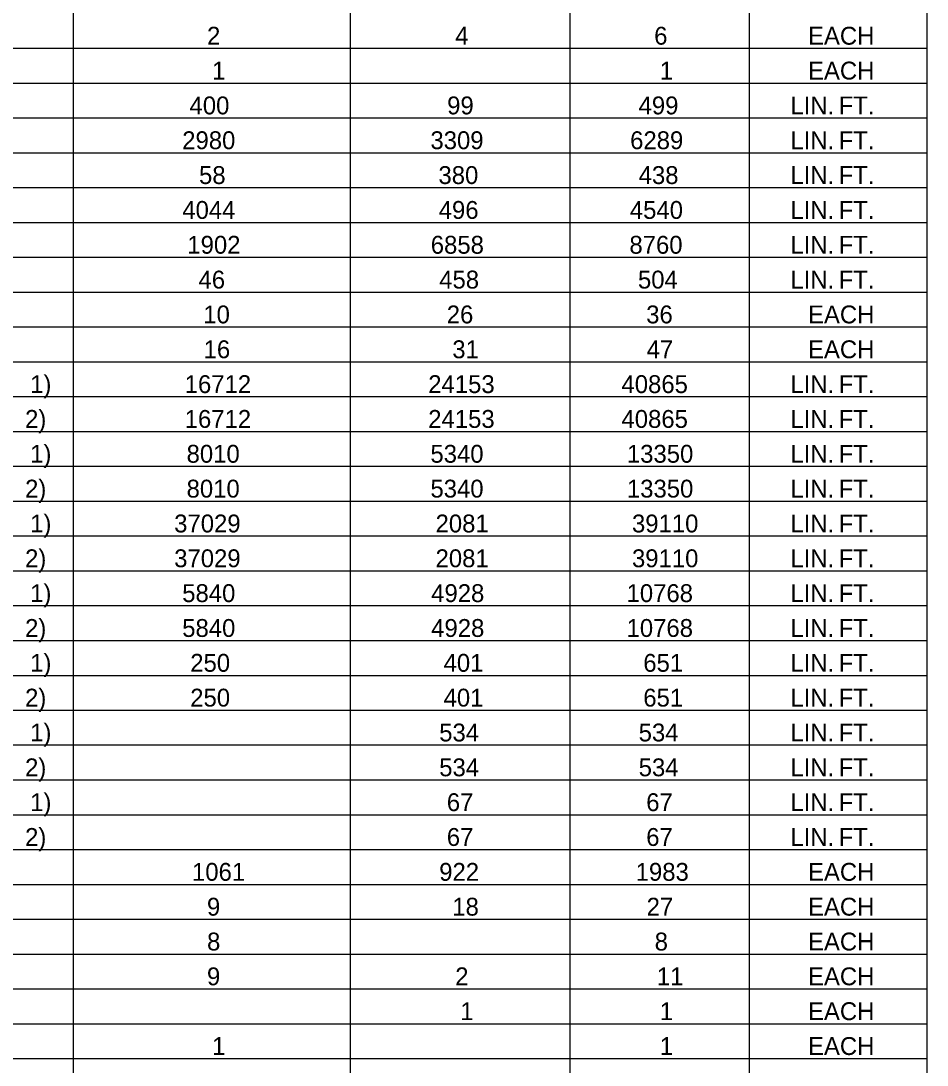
# Model space of a CAD drawing. Extents: x 1226603 to 1228117, y 151305 to 152343.
# Drawn here: x 1227709.6 to 1227925.2, y 151552.9 to 151801.3 of the extents above; entities that cross this region are included whole.
import ezdxf

# ---------------------------------------------------------------- set-up
doc = ezdxf.new("R2010")
doc.units = 0
doc.layers.add('R_Dimension', color=7, linetype='Continuous')

msp = doc.modelspace()

# ---------------------------------------------------------------- linework, layer by layer
at = {"layer": 'R_Dimension'}
for p, q in [((1227722.14, 151330.69), (1227722.14, 152231.95)), ((1227925.18, 151330.69), (1227925.18, 152231.95)), ((1227788.02, 151330.69), (1227788.02, 152217.86)), ((1227840.23, 151330.69), (1227840.23, 152217.86)), ((1227882.92, 151330.69), (1227882.92, 152217.86)), ((1227295.33, 151794.79), (1227925.18, 151794.79)), ((1227295.33, 151786.5), (1227925.18, 151786.5)), ((1227295.33, 151778.21), (1227925.18, 151778.21)), ((1227295.33, 151769.93), (1227925.18, 151769.93)), ((1227295.33, 151761.64), (1227925.18, 151761.64)), ((1227295.33, 151753.35), (1227925.18, 151753.35)), ((1227295.33, 151745.06), (1227925.18, 151745.06)), ((1227295.33, 151736.78), (1227925.18, 151736.78)), ((1227295.33, 151728.49), (1227925.18, 151728.49)), ((1227295.33, 151720.2), (1227925.18, 151720.2)), ((1227295.33, 151711.91), (1227925.18, 151711.91)), ((1227295.33, 151703.63), (1227925.18, 151703.63)), ((1227295.33, 151695.34), (1227925.18, 151695.34)), ((1227295.33, 151687.05), (1227925.18, 151687.05)), ((1227295.33, 151678.76), (1227925.18, 151678.76)), ((1227295.33, 151670.48), (1227925.18, 151670.48)), ((1227295.33, 151662.19), (1227925.18, 151662.19)), ((1227295.33, 151653.9), (1227925.18, 151653.9)), ((1227295.33, 151645.61), (1227925.18, 151645.61)), ((1227295.33, 151637.33), (1227925.18, 151637.33)), ((1227295.33, 151629.04), (1227925.18, 151629.04)), ((1227295.33, 151620.75), (1227925.18, 151620.75)), ((1227295.33, 151612.46), (1227925.18, 151612.46)), ((1227295.33, 151604.18), (1227925.18, 151604.18)), ((1227295.33, 151595.89), (1227925.18, 151595.89)), ((1227295.33, 151587.6), (1227925.18, 151587.6)), ((1227295.33, 151579.31), (1227925.18, 151579.31)), ((1227295.33, 151571.03), (1227925.18, 151571.03)), ((1227295.33, 151562.74), (1227925.18, 151562.74)), ((1227295.33, 151554.45), (1227925.18, 151554.45))]:
    msp.add_line(p, q, dxfattribs=at)

# ---------------------------------------------------------------- texts
for s, p in [('2', (1227753.88, 151795.64)), ('4', (1227812.92, 151795.64)), ('6', (1227860.25, 151795.64)), ('EACH', (1227896.85, 151795.64)), ('1', (1227755.08, 151787.35)), ('1', (1227861.58, 151787.35)), ('EACH', (1227896.85, 151787.35)), ('400', (1227749.71, 151779.06)), ('99', (1227811, 151779.06)), ('499', (1227856.54, 151779.06)), ('LIN.', (1227892.65, 151779.06)), (' FT.', (1227902.56, 151779.06)), ('2980', (1227747.97, 151770.78)), ('3309', (1227807.02, 151770.78)), ('6289', (1227854.53, 151770.78)), ('LIN.', (1227892.65, 151770.78)), (' FT.', (1227902.56, 151770.78)), ('58', (1227751.97, 151762.49)), ('380', (1227808.93, 151762.49)), ('438', (1227856.56, 151762.49)), ('LIN.', (1227892.65, 151762.49)), (' FT.', (1227902.56, 151762.49)), ('4044', (1227747.99, 151754.2)), ('496', (1227808.99, 151754.2)), ('4540', (1227854.46, 151754.2)), ('LIN.', (1227892.65, 151754.2)), (' FT.', (1227902.56, 151754.2)), ('1902', (1227749.19, 151745.91)), ('6858', (1227807.1, 151745.91)), ('8760', (1227854.36, 151745.91)), ('LIN.', (1227892.65, 151745.91)), (' FT.', (1227902.56, 151745.91)), ('46', (1227751.85, 151737.63)), ('458', (1227809.11, 151737.63)), ('504', (1227856.39, 151737.63)), ('LIN.', (1227892.65, 151737.63)), (' FT.', (1227902.56, 151737.63)), ('10', (1227752.99, 151729.34)), ('26', (1227810.9, 151729.34)), ('36', (1227858.35, 151729.34)), ('EACH', (1227896.85, 151729.34)), ('16', (1227753.06, 151721.05)), ('31', (1227812.22, 151721.05)), ('47', (1227858.46, 151721.05)), ('EACH', (1227896.85, 151721.05)), (' 1)', (1227710.22, 151712.76)), ('16712', (1227748.56, 151712.76)), ('24153', (1227806.5, 151712.76)), ('40865', (1227852.47, 151712.76)), ('LIN.', (1227892.65, 151712.76)), (' FT.', (1227902.56, 151712.76)), (' 2)', (1227709.01, 151704.48)), ('16712', (1227748.56, 151704.48)), ('24153', (1227806.5, 151704.48)), ('40865', (1227852.47, 151704.48)), ('LIN.', (1227892.65, 151704.48)), (' FT.', (1227902.56, 151704.48)), (' 1)', (1227710.22, 151696.19)), ('8010', (1227749.01, 151696.19)), ('5340', (1227807.02, 151696.19)), ('13350', (1227853.76, 151696.19)), ('LIN.', (1227892.65, 151696.19)), (' FT.', (1227902.56, 151696.19)), (' 2)', (1227709.01, 151687.9)), ('8010', (1227749.01, 151687.9)), ('5340', (1227807.02, 151687.9)), ('13350', (1227853.76, 151687.9)), ('LIN.', (1227892.65, 151687.9)), (' FT.', (1227902.56, 151687.9)), (' 1)', (1227710.22, 151679.61)), ('37029', (1227746.06, 151679.61)), ('2081', (1227808.24, 151679.61)), ('39110', (1227854.97, 151679.61)), ('LIN.', (1227892.65, 151679.61)), (' FT.', (1227902.56, 151679.61)), (' 2)', (1227709.01, 151671.33)), ('37029', (1227746.06, 151671.33)), ('2081', (1227808.24, 151671.33)), ('39110', (1227854.97, 151671.33)), ('LIN.', (1227892.65, 151671.33)), (' FT.', (1227902.56, 151671.33)), (' 1)', (1227710.22, 151663.04)), ('5840', (1227747.97, 151663.04)), ('4928', (1227807.2, 151663.04)), ('10768', (1227853.68, 151663.04)), ('LIN.', (1227892.65, 151663.04)), (' FT.', (1227902.56, 151663.04)), (' 2)', (1227709.01, 151654.75)), ('5840', (1227747.97, 151654.75)), ('4928', (1227807.2, 151654.75)), ('10768', (1227853.68, 151654.75)), ('LIN.', (1227892.65, 151654.75)), (' FT.', (1227902.56, 151654.75)), (' 1)', (1227710.22, 151646.46)), ('250', (1227749.88, 151646.46)), ('401', (1227810.15, 151646.46)), ('651', (1227857.66, 151646.46)), ('LIN.', (1227892.65, 151646.46)), (' FT.', (1227902.56, 151646.46)), (' 2)', (1227709.01, 151638.18)), ('250', (1227749.88, 151638.18)), ('401', (1227810.15, 151638.18)), ('651', (1227857.66, 151638.18)), ('LIN.', (1227892.65, 151638.18)), (' FT.', (1227902.56, 151638.18)), (' 1)', (1227710.22, 151629.89)), ('534', (1227809.11, 151629.89)), ('534', (1227856.56, 151629.89)), ('LIN.', (1227892.65, 151629.89)), (' FT.', (1227902.56, 151629.89)), (' 2)', (1227709.01, 151621.6)), ('534', (1227809.11, 151621.6)), ('534', (1227856.56, 151621.6)), ('LIN.', (1227892.65, 151621.6)), (' FT.', (1227902.56, 151621.6)), (' 1)', (1227710.22, 151613.31)), ('67', (1227810.92, 151613.31)), ('67', (1227858.36, 151613.31)), ('LIN.', (1227892.65, 151613.31)), (' FT.', (1227902.56, 151613.31)), (' 2)', (1227709.01, 151605.03)), ('67', (1227810.92, 151605.03)), ('67', (1227858.36, 151605.03)), ('LIN.', (1227892.65, 151605.03)), (' FT.', (1227902.56, 151605.03)), ('1061', (1227750.3, 151596.74)), ('922', (1227809.11, 151596.74)), ('1983', (1227855.85, 151596.74)), ('EACH', (1227896.85, 151596.74)), ('9', (1227753.86, 151588.45)), ('18', (1227812.22, 151588.45)), ('27', (1227858.46, 151588.45)), ('EACH', (1227896.85, 151588.45)), ('8', (1227753.88, 151580.16)), ('8', (1227860.37, 151580.16)), ('EACH', (1227896.85, 151580.16)), ('9', (1227753.86, 151571.88)), ('2', (1227812.92, 151571.88)), ('11', (1227860.87, 151571.88)), ('EACH', (1227896.85, 151571.88)), ('1', (1227814.13, 151563.59)), ('1', (1227861.58, 151563.59)), ('EACH', (1227896.85, 151563.59)), ('1', (1227755.08, 151555.3)), ('1', (1227861.58, 151555.3)), ('EACH', (1227896.85, 151555.3))]:
    msp.add_text(s, height=4.25, dxfattribs=at).set_placement(p)

doc.saveas('drawing.dxf')
